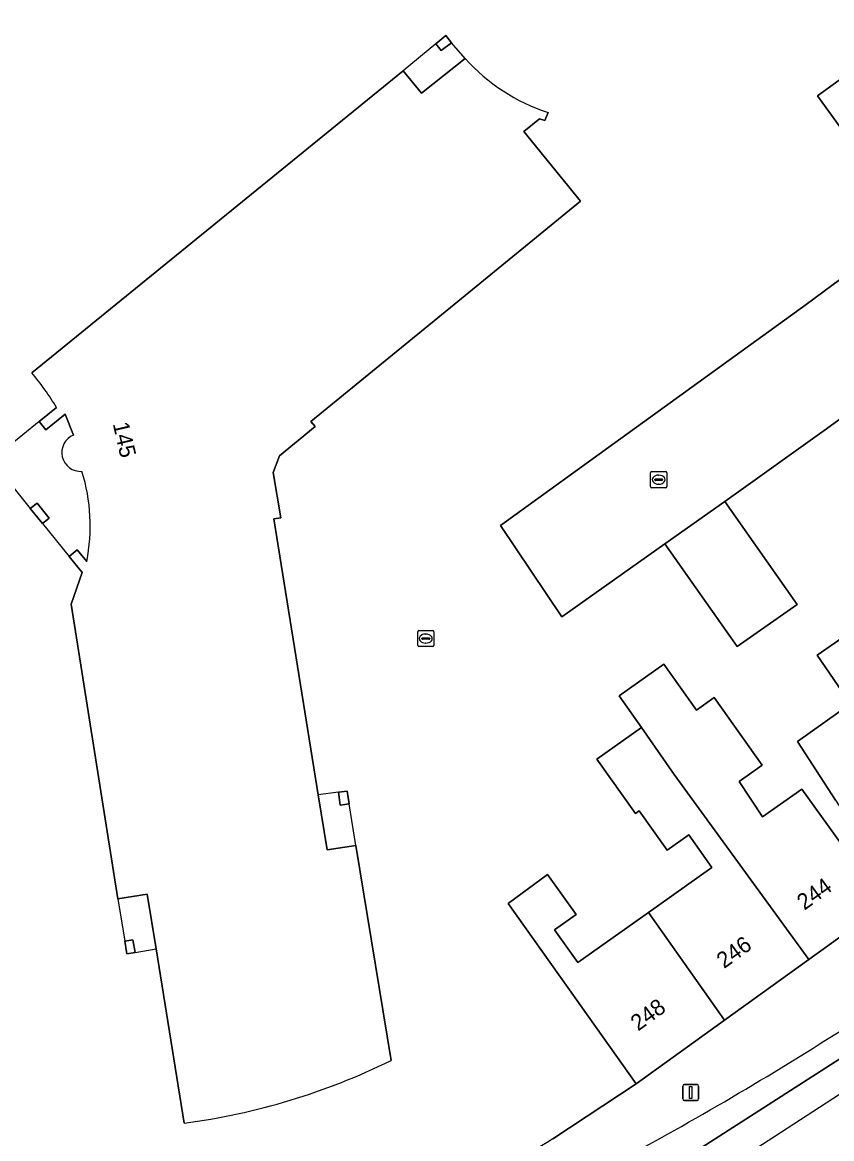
# Model space of a CAD drawing. Extents: x 159262 to 160143, y 383399 to 384319.
# Drawn here: x 159399.7 to 159449.9, y 383448.2 to 383517.5 of the extents above; entities that cross this region are included whole.
import ezdxf

# ---------------------------------------------------------------- set-up
doc = ezdxf.new("R2010")
doc.units = 0
for name, color, linetype in [('IMGEO_Erf', 7, 'Continuous'), ('IMGEO_Kolk', 7, 'Continuous'), ('IMGEO_Lichtmast', 7, 'Continuous'), ('IMGEO_Muur', 7, 'Continuous'), ('IMGEO_Pand', 7, 'Continuous'), ('IMGEO_Pand_nummerreeks', 7, 'Continuous'), ('IMGEO_Pand_overbouw', 7, 'Continuous'), ('IMGEO_Rijbaan_lokaal_gesloten', 7, 'Continuous'), ('IMGEO_Rijbaan_lokaal_open', 7, 'Continuous'), ('IMGEO_Rijbaan_regionaal_open', 7, 'Continuous'), ('IMGEO_Rioolput', 7, 'Continuous'), ('IMGEO_Voetpad_open', 7, 'Continuous')]:
    doc.layers.add(name, color=color, linetype=linetype)

msp = doc.modelspace()

# ---------------------------------------------------------------- linework, layer by layer
at = {"layer": 'IMGEO_Erf'}
for points in [[(159426.287, 383516.236), (159425.636, 383515.758), (159425.297, 383516.165), (159425.927, 383516.689)], [(159458.604, 383507.83), (159454.708, 383505.01), (159448.969, 383512.941), (159452.865, 383515.76)], [(159400.91, 383486.407), (159400.155, 383487.339), (159400.575, 383487.68), (159401.33, 383486.747)], [(159419.929, 383469.01), (159419.383, 383468.939), (159419.279, 383469.732), (159419.804, 383469.8)], [(159406.658, 383459.799), (159406.135, 383459.707), (159406.009, 383460.497), (159406.52, 383460.587)]]:
    msp.add_lwpolyline(points, close=True, dxfattribs=at)
for points in [[(159400.246, 383495.751), (159405.469, 383500), (159423.274, 383514.484), (159424.425, 383513.1), (159427.133, 383515.255)], [(159432.269, 383511.904), (159432.066, 383511.417), (159431.728, 383511.517), (159430.765, 383510.719), (159434.287, 383506.395), (159426.452, 383500), (159417.555, 383492.739), (159417.824, 383492.42), (159415.617, 383490.613), (159415.218, 383489.58), (159415.684, 383486.763), (159415.255, 383486.697), (159418.019, 383469.567), (159418.569, 383466.16)], [(159462.427, 383501.672), (159449.528, 383492.287), (159443.239, 383487.773), (159447.724, 383481.391), (159444.002, 383478.776), (159439.516, 383485.157), (159433.127, 383480.612), (159429.309, 383486.278), (159448.278, 383500), (159458.947, 383507.895)], [(159402.838, 383491.894), (159402.311, 383493.198), (159401.115, 383492.226), (159400.703, 383492.732), (159401.781, 383493.603)], [(159409.695, 383449.207), (159407.956, 383460.026), (159407.41, 383463.425), (159405.588, 383463.126), (159402.681, 383481.403), (159403.364, 383483.376), (159402.564, 383484.363), (159403.07, 383484.772), (159403.655, 383484.049)], [(159450.098, 383469.247), (159447.745, 383472.893), (159451.032, 383475.216), (159448.946, 383478.232), (159453.26, 383481.225)], [(159432.558, 383448.247), (159437.735, 383451.642), (159433.488, 383457.629), (159429.789, 383462.846), (159432.239, 383464.634), (159434.006, 383462.148), (159432.67, 383461.199), (159434.113, 383459.17), (159438.488, 383462.279), (159442.428, 383465.079), (159440.998, 383467.093), (159439.662, 383466.144), (159437.925, 383468.59), (159437.681, 383468.417), (159435.289, 383471.784), (159438.061, 383473.754), (159436.671, 383475.711), (159439.443, 383477.681), (159441.471, 383474.828), (159442.571, 383475.61), (159445.555, 383471.413), (159444.125, 383470.396), (159445.561, 383468.206), (159448.009, 383469.938), (159450.825, 383466.011)], [(159418.569, 383466.16), (159420.335, 383466.43), (159422.526, 383453.101)]]:
    msp.add_lwpolyline(points, dxfattribs=at)
for centre, radius, start, end in [((159435.931, 383523.129), 11.807, 221.8255, 251.92936), ((159388.605, 383485.809), 15.309, 30.6036, 40.49699), ((159403.283, 383490.81), 1.172, 112.33994, 273.84609), ((159392.466, 383486.266), 11.406, 348.79021, 17.20847), ((159404.364, 383489.861), 41.002, 277.47115, 296.29323), ((159387.527, 383521.802), 86.244, 292.74806, 301.4754)]:
    msp.add_arc(centre, radius, start, end, dxfattribs=at)
at = {"layer": 'IMGEO_Kolk'}
for p, q in [((159438.627, 383488.701), (159438.627, 383489.553)), ((159438.702, 383489.627), (159439.554, 383489.627)), ((159438.929, 383489.17), (159439.327, 383489.17)), ((159439.115, 383489.407), (159439.14, 383489.407)), ((159439.628, 383489.553), (159439.628, 383488.701)), ((159439.554, 383488.627), (159438.702, 383488.627)), ((159438.886, 383489.121), (159438.886, 383489.133)), ((159439.324, 383489.084), (159438.926, 383489.084)), ((159439.138, 383488.847), (159439.113, 383488.847)), ((159439.37, 383489.133), (159439.37, 383489.121))]:
    msp.add_line(p, q, dxfattribs=at)
for points in [[(159438.627, 383488.701), (159438.627, 383489.553)], [(159438.702, 383489.627), (159439.554, 383489.627)], [(159439.628, 383489.553), (159439.628, 383488.701)], [(159439.554, 383488.627), (159438.702, 383488.627)]]:
    msp.add_lwpolyline(points, dxfattribs=at)
for centre, radius, start, end in [((159438.704, 383489.551), 0.0765, 91.55205, 178.44795), ((159438.704, 383489.551), 0.0765, 91.55205, 178.44795), ((159438.926, 383489.13), 0.0403, 85.87752, 175.75265), ((159439.331, 383489.132), 0.0386, 1.73085, 96.63898), ((159439.552, 383489.551), 0.0765, 1.55205, 88.44795), ((159439.552, 383489.551), 0.0765, 1.55205, 88.44795), ((159438.704, 383488.703), 0.0765, 181.55205, 268.44795), ((159438.704, 383488.703), 0.0765, 181.55205, 268.44795), ((159438.923, 383489.12), 0.0366, 178.93798, 274.71019), ((159439.327, 383489.127), 0.043, 264.86636, 352.45326), ((159439.552, 383488.703), 0.0765, 271.55205, 358.44795), ((159439.552, 383488.703), 0.0765, 271.55205, 358.44795)]:
    msp.add_arc(centre, radius, start, end, dxfattribs=at)
for centre, major_axis, ratio, start_param, end_param in [((159439.114, 383489.127), (-0.387, 0.002), 0.722429, 4.712389, 7.853982), ((159439.139, 383489.127), (-0.39, 0.002), 0.717154, 1.570796, 4.712389)]:
    msp.add_ellipse(centre, major_axis=major_axis, ratio=ratio, start_param=start_param, end_param=end_param, dxfattribs=at)
at = {"layer": 'IMGEO_Lichtmast'}
for p, q in [((159440.616, 383450.711), (159440.616, 383451.511)), ((159440.616, 383451.511), (159440.616, 383450.711)), ((159440.716, 383451.611), (159441.506, 383451.611)), ((159441.506, 383451.611), (159440.716, 383451.611)), ((159441.606, 383451.511), (159441.606, 383450.711)), ((159441.606, 383450.711), (159441.606, 383451.511)), ((159441.506, 383450.611), (159440.716, 383450.611)), ((159440.716, 383450.611), (159441.506, 383450.611))]:
    msp.add_line(p, q, dxfattribs=at)
msp.add_lwpolyline([(159441.036, 383451.486), (159441.186, 383451.486), (159441.186, 383450.736), (159441.036, 383450.736), (159441.036, 383451.486)], dxfattribs=at)
for centre, start, end in [((159440.716, 383451.511), 90, 180), ((159440.716, 383451.511), 90, 180), ((159441.506, 383451.511), 0, 90), ((159441.506, 383451.511), 360, 90), ((159440.716, 383450.711), 180, 270), ((159440.716, 383450.711), 180, 270), ((159441.506, 383450.711), 270, 0), ((159441.506, 383450.711), 270, 0)]:
    msp.add_arc(centre, 0.1, start, end, dxfattribs=at)
at = {"layer": 'IMGEO_Muur'}
for points in [[(159443.239, 383487.773), (159449.528, 383492.287)], [(159433.127, 383480.612), (159439.516, 383485.157)]]:
    msp.add_lwpolyline(points, dxfattribs=at)
at = {"layer": 'IMGEO_Pand'}
for points in [[(159426.287, 383516.236), (159425.927, 383516.689), (159425.297, 383516.165), (159425.636, 383515.758)], [(159448.969, 383512.941), (159454.708, 383505.01), (159458.604, 383507.83), (159452.865, 383515.76)], [(159400.91, 383486.407), (159401.33, 383486.747), (159400.575, 383487.68), (159400.155, 383487.339)], [(159439.516, 383485.157), (159444.002, 383478.776), (159447.724, 383481.391), (159443.239, 383487.773)], [(159457.797, 383472.131), (159456.764, 383473.668), (159456.127, 383474.578), (159457.221, 383475.501), (159453.26, 383481.225), (159448.946, 383478.232), (159451.032, 383475.216), (159447.745, 383472.893), (159450.098, 383469.247), (159451.881, 383466.465), (159453.93, 383463.377), (159454.645, 383462.299), (159455.487, 383462.857), (159460.48, 383466.17), (159461.322, 383466.728), (159460.521, 383467.934), (159458.557, 383470.895)], [(159450.825, 383466.011), (159448.009, 383469.938), (159445.561, 383468.206), (159444.125, 383470.396), (159445.555, 383471.413), (159442.571, 383475.61), (159441.471, 383474.828), (159439.443, 383477.681), (159436.671, 383475.711), (159438.061, 383473.754), (159440.09, 383470.84), (159448.436, 383459.357), (159453.164, 383462.766), (159453.099, 383462.856)], [(159440.09, 383470.84), (159438.061, 383473.754), (159435.289, 383471.784), (159437.681, 383468.417), (159437.925, 383468.59), (159439.662, 383466.144), (159440.998, 383467.093), (159442.428, 383465.079), (159438.488, 383462.279), (159443.209, 383455.589), (159448.436, 383459.357)], [(159419.279, 383469.732), (159419.383, 383468.939), (159419.929, 383469.01), (159419.804, 383469.8)], [(159438.488, 383462.279), (159434.113, 383459.17), (159432.67, 383461.199), (159434.006, 383462.148), (159432.239, 383464.634), (159429.789, 383462.846), (159433.488, 383457.629), (159437.735, 383451.642), (159443.209, 383455.589)], [(159406.658, 383459.799), (159406.52, 383460.587), (159406.009, 383460.497), (159406.135, 383459.707)]]:
    msp.add_lwpolyline(points, close=True, dxfattribs=at)
for points in [[(159427.133, 383515.255), (159424.425, 383513.1), (159423.274, 383514.484), (159405.469, 383500), (159400.246, 383495.751)], [(159422.526, 383453.101), (159420.335, 383466.43), (159418.569, 383466.16), (159418.019, 383469.567), (159415.255, 383486.697), (159415.684, 383486.763), (159415.218, 383489.58), (159415.617, 383490.613), (159417.824, 383492.42), (159417.555, 383492.739), (159426.452, 383500), (159434.287, 383506.395), (159430.765, 383510.719), (159431.728, 383511.517), (159432.066, 383511.417), (159432.269, 383511.904)], [(159401.781, 383493.603), (159400.703, 383492.732), (159401.115, 383492.226), (159402.311, 383493.198), (159402.838, 383491.894)], [(159403.655, 383484.049), (159403.07, 383484.772), (159402.564, 383484.363), (159403.364, 383483.376), (159402.681, 383481.403), (159405.588, 383463.126), (159407.41, 383463.425), (159407.956, 383460.026), (159409.695, 383449.207)]]:
    msp.add_lwpolyline(points, dxfattribs=at)
for centre, radius, start, end in [((159435.931, 383523.129), 11.807, 221.8255, 251.92936), ((159388.605, 383485.809), 15.309, 30.6036, 40.49699), ((159403.283, 383490.81), 1.172, 112.33994, 273.84609), ((159392.466, 383486.266), 11.406, 348.79021, 17.20847), ((159404.364, 383489.861), 41.002, 277.47115, 296.29323)]:
    msp.add_arc(centre, radius, start, end, dxfattribs=at)
at = {"layer": 'IMGEO_Pand_overbouw'}
for points in [[(159427.133, 383515.255), (159426.287, 383516.236), (159425.636, 383515.758), (159425.297, 383516.165), (159423.274, 383514.484), (159424.425, 383513.1)], [(159420.335, 383466.43), (159419.929, 383469.01), (159419.383, 383468.939), (159419.279, 383469.732), (159418.019, 383469.567), (159418.569, 383466.16)], [(159405.588, 383463.126), (159406.009, 383460.497), (159406.52, 383460.587), (159406.658, 383459.799), (159407.956, 383460.026), (159407.41, 383463.425)]]:
    msp.add_lwpolyline(points, close=True, dxfattribs=at)
for points in [[(159402.838, 383491.894), (159402.311, 383493.198), (159401.115, 383492.226), (159400.703, 383492.732), (159398.671, 383491.079), (159399.081, 383490.575), (159398.561, 383490.167), (159398.907, 383489.739), (159398.487, 383489.399), (159400.155, 383487.339), (159400.575, 383487.68), (159401.33, 383486.747), (159400.91, 383486.407), (159402.564, 383484.363)], [(159402.564, 383484.363), (159403.07, 383484.772), (159403.655, 383484.049)]]:
    msp.add_lwpolyline(points, dxfattribs=at)
for centre, radius, start, end in [((159403.283, 383490.81), 1.172, 112.33994, 273.84609), ((159392.466, 383486.266), 11.406, 348.79021, 17.20847)]:
    msp.add_arc(centre, radius, start, end, dxfattribs=at)
at = {"layer": 'IMGEO_Rijbaan_lokaal_gesloten'}
msp.add_lwpolyline([(159441.755, 383447.67), (159462.471, 383460.966), (159490.279, 383481.992), (159505.707, 383493.657), (159520.375, 383504.829), (159523.234, 383507.076), (159523.45, 383507.257), (159536.444, 383518.15), (159538.496, 383519.827), (159542.031, 383522.493), (159556.314, 383532.084), (159558.176, 383533.322), (159557.167, 383534.781), (159555.701, 383533.767), (159540.95, 383523.893), (159539.823, 383523.091)], dxfattribs=at)
for centre, radius, start, end in [((159107.292, 384003.305), 646.872, 301.695618, 302.311656), ((159340.979, 383625.792), 202.885, 296.92369, 301.55861)]:
    msp.add_arc(centre, radius, start, end, dxfattribs=at)
at = {"layer": 'IMGEO_Rijbaan_lokaal_open'}
msp.add_lwpolyline([(159485.885, 383527.217), (159484.837, 383526.448), (159482.485, 383524.888), (159479.549, 383522.772), (159478.605, 383522.089), (159467.171, 383513.81), (159463.85, 383511.406), (159458.947, 383507.895), (159448.278, 383500), (159429.309, 383486.278), (159433.127, 383480.612), (159439.516, 383485.157), (159443.239, 383487.773), (159449.528, 383492.287), (159462.427, 383501.672), (159473.83, 383510.649)], dxfattribs=at)
at = {"layer": 'IMGEO_Rijbaan_regionaal_open'}
msp.add_lwpolyline([(159401.313, 383419.104), (159430.515, 383438.11), (159440.381, 383444.531), (159453.87, 383453.311), (159490.734, 383481.412), (159490.279, 383481.992), (159462.471, 383460.966), (159441.755, 383447.67), (159418.461, 383435.551)], dxfattribs=at)
at = {"layer": 'IMGEO_Rioolput'}
for p, q in [((159424.183, 383478.844), (159424.183, 383479.696)), ((159424.258, 383479.77), (159425.11, 383479.77)), ((159424.671, 383479.55), (159424.696, 383479.55)), ((159425.184, 383479.696), (159425.184, 383478.844)), ((159424.442, 383479.264), (159424.442, 383479.276)), ((159424.88, 383479.227), (159424.482, 383479.227)), ((159424.485, 383479.313), (159424.883, 383479.313)), ((159424.694, 383478.99), (159424.669, 383478.99)), ((159424.926, 383479.276), (159424.926, 383479.264)), ((159425.11, 383478.77), (159424.258, 383478.77))]:
    msp.add_line(p, q, dxfattribs=at)
for points in [[(159424.183, 383478.844), (159424.183, 383479.696)], [(159424.258, 383479.77), (159425.11, 383479.77)], [(159425.184, 383479.696), (159425.184, 383478.844)], [(159425.11, 383478.77), (159424.258, 383478.77)]]:
    msp.add_lwpolyline(points, dxfattribs=at)
for centre, radius, start, end in [((159424.26, 383479.694), 0.0765, 91.55205, 178.44795), ((159424.26, 383479.694), 0.0765, 91.55205, 178.44795), ((159425.108, 383479.694), 0.0765, 1.55205, 88.44795), ((159425.108, 383479.694), 0.0765, 1.55205, 88.44795), ((159424.26, 383478.846), 0.0765, 181.55205, 268.44795), ((159424.26, 383478.846), 0.0765, 181.55205, 268.44795), ((159424.482, 383479.273), 0.0403, 85.87752, 175.75265), ((159424.479, 383479.263), 0.0366, 178.93798, 274.71019), ((159424.883, 383479.27), 0.043, 264.86636, 352.45326), ((159424.887, 383479.275), 0.0386, 1.73085, 96.63898), ((159425.108, 383478.846), 0.0765, 271.55205, 358.44795), ((159425.108, 383478.846), 0.0765, 271.55205, 358.44795)]:
    msp.add_arc(centre, radius, start, end, dxfattribs=at)
for centre, major_axis, ratio, start_param, end_param in [((159424.67, 383479.27), (-0.387, 0.002), 0.722429, 4.712389, 7.853982), ((159424.695, 383479.27), (-0.39, 0.002), 0.717154, 1.570796, 4.712389)]:
    msp.add_ellipse(centre, major_axis=major_axis, ratio=ratio, start_param=start_param, end_param=end_param, dxfattribs=at)
at = {"layer": 'IMGEO_Voetpad_open'}
msp.add_lwpolyline([(159512.968, 383508.994), (159509.744, 383505.222), (159507.817, 383503.114), (159502.713, 383498.59), (159502.651, 383498.548), (159501.698, 383497.84), (159496.814, 383494.302), (159476.722, 383479.744), (159469.787, 383474.742), (159469.311, 383474.399), (159462.522, 383469.489), (159460.521, 383467.934), (159461.322, 383466.728), (159460.48, 383466.17), (159455.487, 383462.857), (159454.645, 383462.299), (159453.93, 383463.377), (159453.099, 383462.856), (159453.164, 383462.766), (159448.436, 383459.357), (159443.209, 383455.589), (159437.735, 383451.642), (159432.558, 383448.247)], dxfattribs=at)
for centre, radius, start, end in [((159107.292, 384003.305), 646.872, 301.695618, 302.311656), ((159340.979, 383625.792), 202.885, 296.92369, 301.55861), ((159387.527, 383521.802), 86.244, 292.74806, 301.4754)]:
    msp.add_arc(centre, radius, start, end, dxfattribs=at)

# ---------------------------------------------------------------- texts
at = {"layer": 'IMGEO_Pand_nummerreeks'}
for s, rotation, p in [('145', 283.09301, (159405.264, 383492.589)), ('244', 35.99894, (159448.163, 383462.382)), ('246', 36.0104, (159443.182, 383458.762)), ('248', 36.00467, (159437.85, 383454.887))]:
    msp.add_text(s, height=1, rotation=rotation, dxfattribs=at).set_placement(p)

doc.saveas('drawing.dxf')
